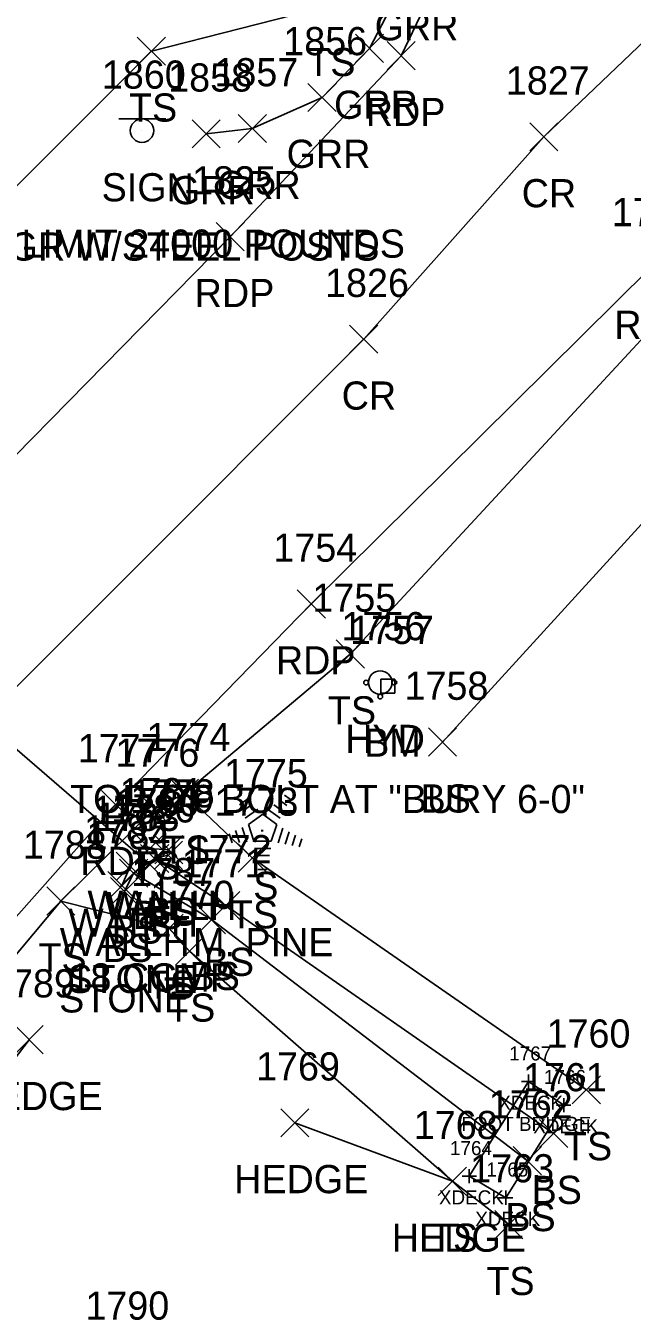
# Model space of a CAD drawing. Extents: x 1600395 to 1603269, y 874955 to 877143.
# Drawn here: x 1601867.3 to 1601910.3, y 875112.5 to 875203.7 of the extents above; entities that cross this region are included whole.
import ezdxf

# ---------------------------------------------------------------- set-up
doc = ezdxf.new("R2010")
doc.units = 0
for name, color, linetype in [('B_A', 7, 'Continuous'), ('B_C', 7, 'Continuous'), ('B_I', 7, 'Continuous'), ('B_TIC', 7, 'Continuous'), ('BELB', 7, 'Continuous'), ('C_A', 7, 'Continuous'), ('C_C', 7, 'Continuous'), ('C_I', 7, 'Continuous'), ('CPBM', 7, 'Continuous'), ('D_A', 7, 'Continuous'), ('D_C', 7, 'Continuous'), ('D_I', 7, 'Continuous'), ('D_TIC', 7, 'Continuous'), ('DCP', 7, 'Continuous'), ('DHW', 7, 'Continuous'), ('L_A', 7, 'Continuous'), ('L_C', 7, 'Continuous'), ('L_I', 7, 'Continuous'), ('L_TIC', 7, 'Continuous'), ('LAHR', 7, 'Continuous'), ('LELB', 7, 'Continuous'), ('LTC', 7, 'Continuous'), ('P_A', 7, 'Continuous'), ('P_I', 7, 'Continuous'), ('P_TIC', 7, 'Continuous'), ('PET', 7, 'Continuous'), ('PRC', 7, 'Continuous'), ('R_A', 7, 'Continuous'), ('R_C', 7, 'Continuous'), ('R_I', 7, 'Continuous'), ('R_TIC', 7, 'Continuous'), ('RGR', 7, 'Continuous'), ('S_A', 7, 'Continuous'), ('S_C', 7, 'Continuous'), ('S_I', 7, 'Continuous'), ('SSGN', 7, 'Continuous'), ('U_A', 7, 'Continuous'), ('U_I', 7, 'Continuous'), ('UWFH', 7, 'Continuous')]:
    doc.layers.add(name, color=color, linetype=linetype)

msp = doc.modelspace()

# ---------------------------------------------------------------- linework, layer by layer
at = {"layer": 'B_TIC'}
for p, q in [((1601902.939, 875128.73), (1601903.014, 875128.73)), ((1601905.433, 875127.062), (1601905.508, 875127.062)), ((1601898.738, 875122.011), (1601898.813, 875122.011)), ((1601901.319, 875120.489), (1601901.394, 875120.489))]:
    msp.add_line(p, q, dxfattribs=at)
for points in [[(1601902.435, 875128.73), (1601903.435, 875128.73)], [(1601902.935, 875128.23), (1601902.935, 875129.23)], [(1601904.929, 875127.062), (1601905.929, 875127.062)], [(1601905.429, 875126.562), (1601905.429, 875127.562)], [(1601898.734, 875121.511), (1601898.734, 875122.511)], [(1601898.234, 875122.011), (1601899.234, 875122.011)], [(1601900.815, 875120.489), (1601901.815, 875120.489)], [(1601901.315, 875119.989), (1601901.315, 875120.989)]]:
    msp.add_lwpolyline(points, dxfattribs=at)
at = {"layer": 'BELB'}
msp.add_lwpolyline([(1601898.734, 875122.011), (1601901.315, 875120.489), (1601905.429, 875127.062), (1601902.935, 875128.73), (1601898.734, 875122.011)], dxfattribs=at)
at = {"layer": 'CPBM'}
for p, q in [((1601892.457, 875156.296), (1601892.457, 875157.296)), ((1601892.457, 875157.296), (1601893.457, 875157.296)), ((1601892.959, 875156.797), (1601892.959, 875156.797)), ((1601892.959, 875156.797), (1601892.959, 875156.797)), ((1601893.457, 875157.296), (1601893.457, 875156.296)), ((1601893.457, 875156.296), (1601892.457, 875156.296))]:
    msp.add_line(p, q, dxfattribs=at)
at = {"layer": 'D_TIC'}
for points in [[(1601875.056, 875144.277), (1601877.056, 875146.277)], [(1601877.056, 875144.277), (1601875.056, 875146.277)], [(1601876.415, 875144.195), (1601878.415, 875146.195)], [(1601878.415, 875144.195), (1601876.415, 875146.195)], [(1601873.683, 875143.019), (1601875.683, 875145.019)], [(1601875.683, 875143.019), (1601873.683, 875145.019)], [(1601875.081, 875143.126), (1601877.081, 875145.126)], [(1601877.081, 875143.126), (1601875.081, 875145.126)], [(1601873.091, 875141.638), (1601875.091, 875143.638)], [(1601875.091, 875141.638), (1601873.091, 875143.638)]]:
    msp.add_lwpolyline(points, dxfattribs=at)
at = {"layer": 'DCP'}
msp.add_lwpolyline([(1601876.081, 875144.126), (1601849.192, 875167.377)], dxfattribs=at)
at = {"layer": 'DHW'}
msp.add_lwpolyline([(1601877.415, 875145.195), (1601876.056, 875145.277), (1601874.683, 875144.019), (1601874.091, 875142.638)], dxfattribs=at)
at = {"layer": 'L_TIC'}
for points in [[(1601875.182, 875200.882), (1601877.182, 875202.882)], [(1601877.182, 875200.882), (1601875.182, 875202.882)], [(1601889.291, 875158.087), (1601891.291, 875160.087)], [(1601891.291, 875158.087), (1601889.291, 875160.087)], [(1601895.83, 875151.834), (1601897.83, 875153.834)], [(1601897.83, 875151.834), (1601895.83, 875153.834)], [(1601877.527, 875148.192), (1601879.527, 875150.192)], [(1601879.527, 875148.192), (1601877.527, 875150.192)], [(1601877.527, 875148.192), (1601879.527, 875150.192)], [(1601879.527, 875148.192), (1601877.527, 875150.192)], [(1601875.374, 875147.082), (1601877.374, 875149.082)], [(1601877.374, 875147.082), (1601875.374, 875149.082)], [(1601875.417, 875143.57), (1601877.417, 875145.57)], [(1601877.417, 875143.57), (1601875.417, 875145.57)], [(1601875.417, 875143.57), (1601877.417, 875145.57)], [(1601877.417, 875143.57), (1601875.417, 875145.57)], [(1601876.38, 875143.797), (1601878.38, 875145.797)], [(1601878.38, 875143.797), (1601876.38, 875145.797)], [(1601882.343, 875143.604), (1601884.343, 875145.604)], [(1601884.343, 875143.604), (1601882.343, 875145.604)], [(1601873.921, 875142.525), (1601875.921, 875144.525)], [(1601875.921, 875142.525), (1601873.921, 875144.525)], [(1601873.921, 875142.525), (1601875.921, 875144.525)], [(1601875.921, 875142.525), (1601873.921, 875144.525)], [(1601873.268, 875141.224), (1601875.268, 875143.224)], [(1601875.268, 875141.224), (1601873.268, 875143.224)], [(1601868.757, 875140.547), (1601870.757, 875142.547)], [(1601870.757, 875140.547), (1601868.757, 875142.547)], [(1601868.757, 875140.547), (1601870.757, 875142.547)], [(1601870.757, 875140.547), (1601868.757, 875142.547)], [(1601880.453, 875140.234), (1601882.453, 875142.234)], [(1601882.453, 875140.234), (1601880.453, 875142.234)], [(1601876.445, 875138.612), (1601878.445, 875140.612)], [(1601878.445, 875138.612), (1601876.445, 875140.612)], [(1601879.448, 875139.23), (1601881.448, 875141.23)], [(1601881.448, 875139.23), (1601879.448, 875141.23)], [(1601877.885, 875136.989), (1601879.885, 875138.989)], [(1601879.885, 875136.989), (1601877.885, 875138.989)], [(1601866.507, 875130.706), (1601868.507, 875132.706)], [(1601868.507, 875130.706), (1601866.507, 875132.706)], [(1601906.04, 875127.146), (1601908.04, 875129.146)], [(1601908.04, 875127.146), (1601906.04, 875129.146)], [(1601885.352, 875124.81), (1601887.352, 875126.81)], [(1601887.352, 875124.81), (1601885.352, 875126.81)], [(1601903.712, 875124.046), (1601905.712, 875126.046)], [(1601905.712, 875124.046), (1601903.712, 875126.046)], [(1601901.851, 875122.113), (1601903.851, 875124.113)], [(1601903.851, 875122.113), (1601901.851, 875124.113)], [(1601896.533, 875120.652), (1601898.533, 875122.652)], [(1601898.533, 875120.652), (1601896.533, 875122.652)], [(1601896.533, 875120.652), (1601898.533, 875122.652)], [(1601898.533, 875120.652), (1601896.533, 875122.652)], [(1601900.535, 875117.578), (1601902.535, 875119.578)], [(1601902.535, 875117.578), (1601900.535, 875119.578)]]:
    msp.add_lwpolyline(points, dxfattribs=at)
at = {"layer": 'LAHR'}
for points in [[(1601867.507, 875131.706), (1601841.948, 875098.173), (1601829.33, 875074.095), (1601820.685, 875054.413), (1601829.051, 875051.14)], [(1601897.533, 875121.652), (1601886.352, 875125.81)]]:
    msp.add_lwpolyline(points, dxfattribs=at)
at = {"layer": 'LELB'}
for points in [[(1602178.369, 875249.145), (1602177.415, 875259.284), (1602168.51, 875260), (1602131.873, 875260.273), (1602108.919, 875258.181), (1602075.252, 875254.524), (1602028.811, 875250.195), (1601991.886, 875244.701), (1601984.631, 875238.194), (1601978.699, 875235.572), (1601960.108, 875224.296), (1601939.912, 875209.734), (1601913.858, 875184.56), (1601890.291, 875159.087), (1601878.527, 875149.192), (1601876.374, 875148.082), (1601869.757, 875141.547), (1601836.036, 875101.247), (1601811.296, 875055.59)], [(1602174.829, 875251.593), (1602174.736, 875253.752), (1602168.055, 875255.411), (1602131.893, 875251.439), (1602109.835, 875249.618), (1602074.671, 875245.332), (1602029.271, 875242.366), (1601990.907, 875234.925), (1601982.234, 875232.995), (1601966.032, 875218.876), (1601945.4, 875204.547), (1601920.127, 875178.351), (1601896.83, 875152.834)], [(1601873.59, 875228.471), (1601886.316, 875227.217), (1601889.851, 875219.333), (1601888.826, 875205.111), (1601876.182, 875201.882), (1601861.198, 875186.913), (1601855.268, 875169.635), (1601851.422, 875163.08), (1601832.365, 875146.425)], [(1601907.04, 875128.146), (1601883.343, 875144.604), (1601878.527, 875149.192)], [(1601904.712, 875125.046), (1601881.453, 875141.234), (1601876.417, 875144.57), (1601874.921, 875143.525), (1601874.268, 875142.224)], [(1601877.38, 875144.797), (1601876.417, 875144.57)], [(1601902.851, 875123.113), (1601880.448, 875140.23), (1601874.921, 875143.525)], [(1601901.535, 875118.578), (1601897.533, 875121.652), (1601878.885, 875137.989), (1601877.445, 875139.612), (1601869.757, 875141.547)]]:
    msp.add_lwpolyline(points, dxfattribs=at)
at = {"layer": 'LTC'}
for p, q in [((1601882.213, 875148.836), (1601882.568, 875149.093)), ((1601882.423, 875148.37), (1601882.952, 875148.755)), ((1601885.24, 875148.728), (1601885.79, 875148.329)), ((1601885.612, 875149.076), (1601886.031, 875148.772)), ((1601882.632, 875147.905), (1601883.336, 875148.416)), ((1601882.842, 875147.439), (1601883.72, 875148.077)), ((1601883.067, 875146.984), (1601884.078, 875147.718)), ((1601884.078, 875147.718), (1601885.075, 875146.993)), ((1601884.498, 875148.031), (1601885.308, 875147.443)), ((1601884.87, 875148.38), (1601885.549, 875147.886)), ((1601882.612, 875146.765), (1601882.943, 875145.745)), ((1601883.067, 875146.984), (1601883.454, 875145.79)), ((1601885.075, 875146.993), (1601884.684, 875145.79)), ((1601881.246, 875146.115), (1601881.398, 875145.647)), ((1601881.701, 875146.332), (1601881.913, 875145.68)), ((1601882.157, 875146.548), (1601882.428, 875145.713)), ((1601885.513, 875146.723), (1601885.175, 875145.683)), ((1601885.957, 875146.472), (1601885.67, 875145.588)), ((1601886.402, 875146.222), (1601886.165, 875145.493)), ((1601886.846, 875145.972), (1601886.66, 875145.398)), ((1601884.684, 875145.79), (1601883.454, 875145.79)), ((1601884.646, 875145.29), (1601883.501, 875145.29)), ((1601884.562, 875144.79), (1601883.574, 875144.79)), ((1601884.478, 875144.29), (1601883.647, 875144.29)), ((1601884.395, 875143.79), (1601883.72, 875143.79))]:
    msp.add_line(p, q, dxfattribs=at)
at = {"layer": 'P_TIC'}
for points in [[(1601892.902, 875200.56), (1601894.902, 875202.56)], [(1601894.902, 875200.56), (1601892.902, 875202.56)], [(1601903.017, 875194.801), (1601905.017, 875196.801)], [(1601905.017, 875194.801), (1601903.017, 875196.801)], [(1601880.764, 875187.712), (1601882.764, 875189.712)], [(1601882.764, 875187.712), (1601880.764, 875189.712)], [(1601890.245, 875180.434), (1601892.245, 875182.434)], [(1601892.245, 875180.434), (1601890.245, 875182.434)], [(1601886.524, 875161.64), (1601888.524, 875163.64)], [(1601888.524, 875161.64), (1601886.524, 875163.64)], [(1601872.649, 875147.403), (1601874.649, 875149.403)], [(1601874.649, 875147.403), (1601872.649, 875149.403)]]:
    msp.add_lwpolyline(points, dxfattribs=at)
at = {"layer": 'PET'}
for points in [[(1601981.363, 875249.806), (1601972.89, 875242.44), (1601955.896, 875227.486), (1601938.248, 875211.842), (1601911.531, 875186.457), (1601887.524, 875162.64), (1601873.649, 875148.403), (1601834.558, 875104.332), (1601817.898, 875080.131), (1601806.172, 875058.569), (1601796.417, 875036.344), (1601789.601, 875012.3), (1601785.899, 874989.711)], [(1601764.4, 874992.239), (1601768.772, 875018.84), (1601777.997, 875048.131), (1601790.928, 875076.192), (1601810.073, 875107.229), (1601828.654, 875131.775), (1601847.507, 875153.359), (1601863.919, 875170.533), (1601881.764, 875188.712), (1601893.902, 875201.56), (1601897.71, 875209.517), (1601897.173, 875214.832), (1601896.079, 875222.115), (1601893.32, 875227.875), (1601887.406, 875234.65), (1601882.142, 875236.788)]]:
    msp.add_lwpolyline(points, dxfattribs=at)
at = {"layer": 'PRC'}
msp.add_lwpolyline([(1601775.553, 874992.017), (1601780.37, 875017.597), (1601787.983, 875044.4), (1601800.395, 875072.616), (1601818.138, 875100.611), (1601837.005, 875125.104), (1601855.239, 875145.384), (1601891.245, 875181.434), (1601904.017, 875195.801), (1601914.312, 875205.653), (1601919.011, 875213.201), (1601928.745, 875226.855), (1601931.003, 875235.476), (1601931.432, 875243.625)], dxfattribs=at)
at = {"layer": 'R_TIC'}
for points in [[(1601890.648, 875201.079), (1601892.648, 875203.079)], [(1601892.648, 875201.079), (1601890.648, 875203.079)], [(1601887.283, 875197.595), (1601889.283, 875199.595)], [(1601889.283, 875197.595), (1601887.283, 875199.595)], [(1601879.064, 875195.015), (1601881.064, 875197.015)], [(1601881.064, 875195.015), (1601879.064, 875197.015)], [(1601882.339, 875195.387), (1601884.339, 875197.387)], [(1601884.339, 875195.387), (1601882.339, 875197.387)]]:
    msp.add_lwpolyline(points, dxfattribs=at)
at = {"layer": 'RGR'}
msp.add_lwpolyline([(1601873.114, 875234.711), (1601878.69, 875234.931), (1601884.672, 875234.178), (1601889.161, 875231.819), (1601892.939, 875227.226), (1601895.36, 875221.061), (1601895.948, 875213.854), (1601894.529, 875207.643), (1601891.648, 875202.079), (1601888.283, 875198.595), (1601883.339, 875196.387), (1601880.064, 875196.015)], dxfattribs=at)
at = {"layer": 'SSGN'}
for p, q in [((1601873.865, 875197.073), (1601877.199, 875197.073)), ((1601875.512, 875196.24), (1601875.512, 875196.24))]:
    msp.add_line(p, q, dxfattribs=at)
msp.add_circle((1601875.512, 875196.24), 0.833, dxfattribs=at)
at = {"layer": 'UWFH'}
msp.add_line((1601892.413, 875157.063), (1601892.413, 875157.063), dxfattribs=at)
for centre, radius in [((1601892.413, 875157.063), 0.833), ((1601891.413, 875157.063), 0.167), ((1601893.413, 875157.063), 0.167), ((1601892.413, 875156.063), 0.167)]:
    msp.add_circle(centre, radius, dxfattribs=at)

# ---------------------------------------------------------------- texts
at = {"layer": 'B_A'}
for p in [(1601900.778, 875126.73), (1601903.272, 875125.062), (1601896.577, 875120.011), (1601899.158, 875118.489)]:
    msp.add_text('XDECK', height=1, dxfattribs=at).set_placement(p)
at = {"layer": 'B_C'}
msp.add_text('FOOT BRIDGE', height=1, dxfattribs=at).set_placement((1601898.172, 875125.23))
at = {"layer": 'B_I'}
for s, p in [('1767', (1601901.565, 875130.23)), ('1766', (1601904.032, 875128.562)), ('1764', (1601897.364, 875123.511)), ('1765', (1601899.945, 875121.989))]:
    msp.add_text(s, height=1, dxfattribs=at).set_placement(p)
at = {"layer": 'C_A'}
msp.add_text('BM', height=2, dxfattribs=at).set_placement((1601891.274, 875151.797))
at = {"layer": 'C_C'}
msp.add_text('TOP OF BOLT AT "BURY 6-0"', height=2, dxfattribs=at).set_placement((1601870.409, 875147.797))
at = {"layer": 'C_I'}
msp.add_text('1757', height=2, dxfattribs=at).set_placement((1601890.267, 875159.797))
at = {"layer": 'D_A'}
for s, p in [('WALLH', (1601871.647, 875140.277)), ('WALLH', (1601873.005, 875140.195)), ('WALLH', (1601870.274, 875139.019)), ('P', (1601875.459, 875139.126)), ('WALLH', (1601869.682, 875137.638))]:
    msp.add_text(s, height=2, dxfattribs=at).set_placement(p)
at = {"layer": 'D_C'}
for s, p in [('STONE', (1601870.226, 875135.019)), ('18 CGMP', (1601870.372, 875135.126)), ('STONE', (1601869.635, 875133.638))]:
    msp.add_text(s, height=2, dxfattribs=at).set_placement(p)
at = {"layer": 'D_I'}
for s, p in [('1781', (1601873.93, 875148.277)), ('1778', (1601874.722, 875148.195)), ('1782', (1601871.99, 875147.019)), ('1786', (1601873.333, 875147.126)), ('1785', (1601871.399, 875145.638))]:
    msp.add_text(s, height=2, dxfattribs=at).set_placement(p)
at = {"layer": 'L_A'}
for s, p in [('TS', (1601887.235, 875200.111)), ('TS', (1601874.591, 875196.882)), ('TS', (1601888.7, 875154.087)), ('BS', (1601895.271, 875147.834)), ('TS', (1601876.937, 875144.192)), ('TS', (1601876.937, 875144.192)), ('TS', (1601874.783, 875143.082)), ('S', (1601883.404, 875141.628)), ('BS', (1601874.858, 875139.57)), ('BS', (1601874.858, 875139.57)), ('BS', (1601875.821, 875139.797)), ('TS', (1601881.753, 875139.604)), ('BS', (1601873.362, 875138.525)), ('BS', (1601873.362, 875138.525)), ('TS', (1601868.166, 875136.547)), ('TS', (1601868.166, 875136.547)), ('BS', (1601872.709, 875137.224)), ('BS', (1601879.894, 875136.234)), ('BS', (1601878.889, 875135.23)), ('TS', (1601875.854, 875134.612)), ('TS', (1601877.295, 875132.989)), ('HEDGE', (1601863.207, 875126.706)), ('TS', (1601905.449, 875123.146)), ('HEDGE', (1601882.053, 875120.81)), ('BS', (1601903.153, 875120.046)), ('BS', (1601901.292, 875118.113)), ('HEDGE', (1601893.234, 875116.652)), ('TS', (1601895.943, 875116.652)), ('TS', (1601899.944, 875113.578))]:
    msp.add_text(s, height=2, dxfattribs=at).set_placement(p)
at = {"layer": 'L_C'}
msp.add_text('M. PINE', height=2, dxfattribs=at).set_placement((1601879.136, 875137.628))
at = {"layer": 'L_I'}
for s, p in [('1755', (1601887.598, 875162.087)), ('1758', (1601894.138, 875155.834)), ('1774', (1601875.835, 875152.192)), ('1774', (1601875.835, 875152.192)), ('1776', (1601873.626, 875151.082)), ('1775', (1601881.325, 875149.628)), ('1780', (1601873.638, 875147.57)), ('1780', (1601873.638, 875147.57)), ('1779', (1601874.679, 875147.797)), ('1773', (1601880.651, 875147.604)), ('1783', (1601872.228, 875146.525)), ('1783', (1601872.228, 875146.525)), ('1784', (1601871.575, 875145.224)), ('1788', (1601867.064, 875144.547)), ('1788', (1601867.064, 875144.547)), ('1772', (1601878.761, 875144.234)), ('1771', (1601878.322, 875143.23)), ('1787', (1601874.752, 875142.612)), ('1770', (1601876.106, 875140.989)), ('1789', (1601864.806, 875134.706)), ('1760', (1601904.213, 875131.146)), ('1769', (1601883.604, 875128.81)), ('1761', (1601902.539, 875128.046)), ('1762', (1601900.111, 875126.113)), ('1768', (1601894.793, 875124.652)), ('1768', (1601894.793, 875124.652)), ('1763', (1601898.795, 875121.578)), ('1790', (1601871.498, 875111.83))]:
    msp.add_text(s, height=2, dxfattribs=at).set_placement(p)
at = {"layer": 'LTC'}
msp.add_text('.', height=1.037, rotation=270, dxfattribs=at).set_placement((1601883.961, 875146.732))
at = {"layer": 'P_A'}
for s, p in [('RDP', (1601891.391, 875196.56)), ('CR', (1601902.45, 875190.801)), ('RDP', (1601879.252, 875183.712)), ('RDP', (1601909.019, 875181.457)), ('CR', (1601889.679, 875176.434)), ('RDP', (1601885.012, 875157.64)), ('RDP', (1601871.137, 875143.403))]:
    msp.add_text(s, height=2, dxfattribs=at).set_placement(p)
at = {"layer": 'P_I'}
for s, p in [('1827', (1601901.325, 875198.801)), ('1825', (1601879.071, 875191.712)), ('1753', (1601908.838, 875189.457)), ('1826', (1601888.498, 875184.434)), ('1754', (1601884.831, 875165.64)), ('1777', (1601870.956, 875151.403))]:
    msp.add_text(s, height=2, dxfattribs=at).set_placement(p)
at = {"layer": 'R_A'}
for p in [(1601892.017, 875202.643), (1601889.136, 875197.079), (1601885.771, 875193.595), (1601880.827, 875191.387), (1601877.552, 875191.015)]:
    msp.add_text('GRR', height=2, dxfattribs=at).set_placement(p)
at = {"layer": 'R_C'}
msp.add_text('SGR W/STEEL POSTS', height=2, dxfattribs=at).set_placement((1601864.269, 875187.015))
at = {"layer": 'R_I'}
for s, p in [('1856', (1601885.535, 875201.595)), ('1858', (1601877.371, 875199.015)), ('1857', (1601880.646, 875199.387))]:
    msp.add_text(s, height=2, dxfattribs=at).set_placement(p)
at = {"layer": 'S_A'}
msp.add_text('SIGN', height=2, dxfattribs=at).set_placement((1601872.65, 875191.22))
at = {"layer": 'S_C'}
msp.add_text('LEGAL LOAD LIMIT 24000 POUNDS', height=2, dxfattribs=at).set_placement((1601849.572, 875187.22))
at = {"layer": 'S_I'}
msp.add_text('1860', height=2, dxfattribs=at).set_placement((1601872.666, 875199.22))
at = {"layer": 'U_A'}
msp.add_text('HYD', height=2, dxfattribs=at).set_placement((1601889.933, 875152.063))
at = {"layer": 'U_I'}
msp.add_text('1756', height=2, dxfattribs=at).set_placement((1601889.665, 875160.063))

doc.saveas('drawing.dxf')
